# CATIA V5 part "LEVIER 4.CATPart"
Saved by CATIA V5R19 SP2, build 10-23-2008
Part number: LEVIER 4
Bounding box of the stored display mesh (mm): x -7.702 to 7.702, y -37.709 to 2.5, z 0 to 23
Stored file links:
  U:\IAO\Nouveau dossier\LEVIER 4.CATPart
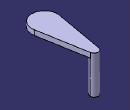
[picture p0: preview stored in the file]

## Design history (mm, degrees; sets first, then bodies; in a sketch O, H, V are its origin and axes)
Body1 (main body)
  Sketch1 on xy-plane, origin (0, 0, 0), H (1, 0, 0), V (0, 1, 0)
    circle A1 centre (0, 0) radius 2.5
    radius A1 = 2.5
  Pad1: profile Sketch1, direction (0, 0, 1), length 20
  Sketch2 on end face of Pad1, origin (0, 0, 20), H (1, 0, 0), V (0, 1, 0)
    arc A1 centre (0, 0) radius 2.5 from (2.462, 0.4341) to (-2.462, 0.4341) ccw
    reference projected circle E1 centre (0, 0) radius 2.5 from edge [face of Pad1 from Sketch1.A1 | end face of Pad1]
    reference projected circle E2 centre (0, 0) radius 2.5 from edge [face of Pad1 from Sketch1.A1 | end face of Pad1]
    line L1 (-2.462, 0.4341) -> (-7.5923, -28.6613)
    point P1 (-2.462, 0.4341)
    point P2 (-7.5923, -28.6613)
    point P3 (7.5923, -28.6613)
    point P4 (2.462, 0.4341)
    line L2 (2.462, 0.4341) -> (7.5923, -28.6613)
    arc A2 centre (0, -30) radius 7.7094 from (-7.5923, -28.6613) to (7.5923, -28.6613) ccw
    point P5 (0, -30)
    angle V L1 = 10
    distance P5 H = 30
    concentricity: A1 E1
    coincidence: A1 E2
    tangency: L1 A1, A2 L2, A2 L1
    symmetry: P2 P3 V, P1 P4 V, L1 L2 V
  Pad2: profile Sketch2, direction (0, 0, 1), length 3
